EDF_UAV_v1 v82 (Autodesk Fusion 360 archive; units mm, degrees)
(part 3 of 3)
sketch "Sketch1" plane through (0, 0, 0) normal (0, 1, 0) x axis (1, 0, 0)
  line L1 (-11.4, 0) -> (-11.4, -16.82)
  line L2 (11.4, 0) -> (-11.4, 0)
  line L3 (11.4, -16.82) -> (11.4, 0)
  line L4 (16.2, -16.82) -> (11.4, -16.82)
  line L5 (16.2, -19.22) -> (16.2, -16.82)
  line L6 (11.4, -19.22) -> (16.2, -19.22)
  line L7 (11.4, -25.4) -> (11.4, -19.22)
  line L8 (-11.4, -25.4) -> (11.4, -25.4)
  line L9 (-11.4, -19.22) -> (-11.4, -25.4)
  line L10 (-16.2, -19.22) -> (-11.4, -19.22)
  line L11 (-16.2, -16.82) -> (-16.2, -19.22)
  line L12 (-16.2, -16.82) -> (-11.4, -16.82)
  line L13 (0, -22.5) -> (0, -1.75)
  point P1 (0, 0)
  point P3 (-11.4, 0)
  point P4 (11.4, 0)
  point P5 (11.4, -16.82)
  point P6 (16.2, -16.82)
  point P7 (16.2, -19.22)
  vertical L1
  perpendicular L1 L2
  perpendicular L2 L3
  perpendicular L3 L4
  perpendicular L4 L5
  perpendicular L5 L6
  perpendicular L6 L7
  perpendicular L7 L8
  perpendicular L8 L9
  perpendicular L9 L10
  perpendicular L10 L11
  perpendicular L11 L12
  equal L4 L12
  equal L2 L8
  collinear L1 L9
  equal L5 L11
  equal L1 L3
  coincident P1 L2
  symmetric L1 L3 L13
  dimension "d1" distance P3 P4 = 22.8
  dimension "d2" distance P4 P5 = 16.82
  dimension "d4" distance L5 L11 = 32.4
  dimension "d5" distance L2 L8 = 25.4
  dimension "d6" distance P6 P7 = 2.4
extrude "Extrude1" new body sketch "Sketch1" profile of L1 L2 L3 L4 L5 L6 L7 L8 L9 L10 L11 L12 distance 12
sketch "Sketch2" plane through (0, 0, 19.22) normal (0, 0, 1) x axis (-1, 0, 0)
  line L1 (11.4, -6) -> (11.4, 6)
  line L2 (16.2, -6) -> (11.4, -6)
  line L3 (16.2, 6) -> (16.2, -6)
  line L4 (11.4, 6) -> (16.2, 6)
  line L5 (0, -22.5) -> (0, -1.75)
  line L6 (-14.2, 0) -> (14.2, 0)
  line L7 (-22.5, 0) -> (-1.75, 0)
  circle C1 centre (14.2, 0) radius 1.25
  circle C2 centre (-14.2, 0) radius 1.25
  point P6 (14.2, 0)
  point P7 (-14.2, 0)
  point P10 (14.2, 0)
  point P11 (-14.2, 0)
  equal C1 C2
  symmetric P6 P7 L5
  coincident P6 P10
  coincident P7 P11
  collinear L6 L7
  dimension "d9" diameter C2 = 2.5
  dimension "d10" distance P6 P7 = 28.4
extrude "Extrude2" cut sketch "Sketch2" profile of C1 C2 L7 no distance stored
sketch "Sketch3" plane through (0, 0, 25.4) normal (0, 0, 1) x axis (-1, 0, 0)
  line L1 (-11.4, -6) -> (-11.4, 6)
  line L2 (11.4, -6) -> (-11.4, -6)
  line L3 (11.4, 6) -> (11.4, -6)
  line L4 (-11.4, 6) -> (11.4, 6)
  line L5 (0.4768, -1.75) -> (-0.6, -1.75)
  line L6 (0.4768, 1.75) -> (-0.6, 1.75)
  line L7 (-22.5, 0) -> (-1.75, 0)
  arc A1 centre (-0.6, 0) radius 1.75 clockwise from (-0.6, -1.75) to (-0.6, 1.75)
  arc A2 centre (5.4, 0) radius 5.225 clockwise from (0.4768, 1.75) to (0.4768, -1.75)
  point P7 (-0.6, 0)
  point P6 (5.4, 0)
  horizontal L5
  parallel L5 L6
  tangent L5 A1
  tangent L6 A1
  coincident P7 L7
  coincident P6 L7
  dimension "d14" diameter A2 = 10.45
  dimension "d15" distance L1 P6 = 16.8
  dimension "d21" diameter A1 = 3.5
  dimension "d22" distance P6 P7 = 6
extrude "Extrude4" cut sketch "Sketch3" profile of L1 L2 L3 L4 A2 against normal blind 0.5
sketch "Sketch5" plane through (0, 0, 25.4) normal (0, 0, 1) x axis (-1, 0, 0)
  line L1 (0.4768, -1.75) -> (-0.6, -1.75)
  line L2 (0.4768, 1.75) -> (-0.6, 1.75)
  circle C1 centre (5.4, 0) radius 4.5
  arc A1 centre (5.4, 0) radius 5.225 clockwise from (0.4768, 1.75) to (0.4768, -1.75)
  arc A2 centre (5.4, 0) radius 5.225 clockwise from (0.4768, 1.75) to (0.4768, -1.75)
  arc A3 centre (-0.6, 0) radius 1.75 clockwise from (-0.6, -1.75) to (-0.6, 1.75)
  concentric C1 A1
  dimension "d23" diameter C1 = 9
extrude "Extrude6" cut sketch "Sketch5" against normal blind 0.3
chamfer "Chamfer1" distance 0.5
chamfer "Chamfer2" distance 4 distance 1.5
sketch "Sketch6" plane through (0, 0, 25.4) normal (0, 0, 1) x axis (-1, 0, 0)
  circle C1 centre (5.4, 0) radius 4.5
  circle C2 centre (5.4, 0) radius 2.5
  concentric C1 C2
  dimension "d29" diameter C2 = 5
extrude "Extrude7" add sketch "Sketch6" profile of C2 along normal blind 2.8
chamfer "Chamfer3" distance 0.1
work_axis "WorkAxis1"
hole "Hole1" HoleDepth 3 HoleDiameter 1.271 TipAngle 118
sketch "Sketch1" plane through (0, 0, 28.2) normal (0, 0, 1) x axis (-1, 0, 0)
  circle C1 centre (5.4, 0) radius 2.5
  circle C2 centre (5.4, 0) radius 9.95
  circle C3 centre (5.4, 0) radius 3.5
  circle C4 centre (5.4, 0) radius 0.6355
  circle C5 centre (5.4, 0) radius 0.6355
  circle C6 centre (5.4, 0) radius 2.5
  concentric C1 C2
  concentric C1 C3
  concentric C1 C4
  equal C4 C5
  equal C1 C6
  concentric C3 C6
  dimension "d36" diameter C2 = 19.9
  dimension "d37" diameter C3 = 7
extrude "Extrude1" new body sketch "Sketch1" profile of C1 C3 against normal blind 2.4
extrude "Extrude2" add sketch "Sketch1" profile of C1 C2 C3 C4 C5 along normal blind 1.35
chamfer "Chamfer1" distance 1
sketch "Sketch2" plane through (0, 0, 29.55) normal (0, 0, 1) x axis (-1, 0, 0)
  line L1 (20.6977, 0) -> (5.4, 0)
  circle C1 centre (5.4, 0) radius 9.95
  circle C2 centre (5.4, 0) radius 1.6355
  circle C3 centre (5.4, 0) radius 4.5
  circle C4 centre (5.4, 0) radius 6.5
  circle C5 centre (5.4, 0) radius 8.5
  circle C6 centre (13.9, 0) radius 0.5
  circle C7 centre (11.9, 0) radius 0.5
  circle C8 centre (9.9, 0) radius 0.5
  point P4 (5.4, 0)
  point P6 (5.4, 0)
  point P8 (13.9, 0)
  point P9 (11.9, 0)
  point P10 (9.9, 0)
  concentric C1 C3
  concentric C3 C4
  concentric C3 C5
  coincident P4 P6
  horizontal L1
  coincident C5 P8
  coincident L1 P8
  coincident L1 P9
  coincident C4 P9
  coincident L1 P10
  coincident C3 P10
  equal C6 C7
  equal C6 C8
  dimension "d43" diameter C3 = 9
  dimension "d44" diameter C4 = 13
  dimension "d45" diameter C5 = 17
  dimension "d46" diameter C6 = 1
extrude "Extrude3" cut sketch "Sketch2" profile of C6 C7 C8 to an object
circular_pattern "C-Pattern1" TotalAngle 360
position "Position1"
joint "Assemble1" alignAngle 0 alignOffsetX 0 alignOffsetY 0 alignOffsetZ 0
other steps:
thread "Thread1"
create_component "CreateComponent1"
joint_origin "JointOrigin1"
joint_origin "JointOrigin1"

design "UAV_test_rig"
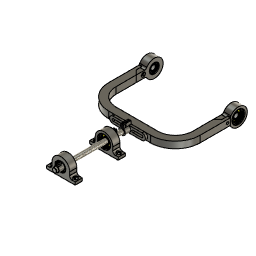
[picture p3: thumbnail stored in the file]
sketch "Sketch1" plane through (0, 0, 0) normal (0, 1, 0) x axis (1, 0, 0)
  line L1 (0, -39) -> (0, 16)
  line L2 (-16, -5) -> (-16, -16)
  line L3 (-26, -5) -> (-16, -5)
  line L4 (-26, 0) -> (-26, -5)
  line L5 (26, 0) -> (-26, 0)
  line L6 (26, -5) -> (26, 0)
  line L7 (16, -5) -> (26, -5)
  line L8 (16, -16) -> (16, -5)
  circle C1 centre (0, -16) radius 11.1
  arc A1 centre (0, -16) radius 16 clockwise from (16, -16) to (-16, -16)
  circle C2 centre (0, -16) radius 9
  point P1 (0, 0)
  point P2 (0, -16)
  point P8 (-26, -5)
  point P9 (-26, 0)
  vertical L1
  coincident P1 L1
  coincident P2 L1
  concentric C1 A1
  vertical L2
  perpendicular L2 L3
  perpendicular L3 L4
  perpendicular L1 L5
  perpendicular L3 L6
  perpendicular L1 L7
  tangent L2 A1
  tangent L8 A1
  vertical L8
  equal L3 L7
  equal L4 L6
  coincident P1 L5
  concentric C1 C2
  dimension "d1" diameter C1 = 22.2
  dimension "d2" distance P8 P9 = 5
  dimension "d3" distance L4 L6 = 52
  dimension "d4" distance P2 L5 = 16
  dimension "d10" diameter C2 = 18
  dimension "d68" diameter A1 = 32
extrude "Extrude1" new body sketch "Sketch1" profile of C1 A1 L2 L3 L4 L5 L6 L7 L8 along normal blind 13
fillet "Fillet1" radius 5
extrude "Extrude3" cut sketch "Sketch1" profile of C2 no distance stored
extrude "Extrude2" cut sketch "Sketch1" profile of C1 along normal blind 11
chamfer "Chamfer1" distance 1
chamfer "Chamfer2" distance 1 Rotate Angle 10
work_plane "WorkPlane2" AlongDistance 16
sketch "Sketch3" plane through (0, 0, 16) normal (0, 0, 1) x axis (1, 0, 0)
  line L1 (11.5, 3.9) -> (11.1, 3.9)
  line L2 (11.5, 2.8) -> (11.5, 3.9)
  line L3 (11.1, 2.8) -> (11.5, 2.8)
  line L4 (11.1, 3.9) -> (11.1, 2.8)
  line L5 (-11.1, 11) -> (11.1, 11)
  line L6 (11.1, -3.2011) -> (11.1, 11)
  line L7 (0, -3.5) -> (0, 0)
  line L8 (11.1, 2.4) -> (11.5, 2.8)
  line L9 (11.1, 2.8) -> (11.1, 2.4)
  point P6 (11.1, 11)
  point P8 (11.1, 11)
  point P1 (0, 0)
  point P10 (0, 0)
  point P12 (11.1, 2.4)
  point P3 (11.5, 3.9)
  point P4 (11.5, 2.8)
  horizontal L1
  vertical L2
  horizontal L3
  vertical L4
  coincident P6 P8
  perpendicular L5 L6
  collinear L4 L6
  coincident P1 P10
  vertical L7
  coincident L6 P12
  dimension "d17" distance L1 L5 = 7.1
  dimension "d18" = 23
  dimension "d19" distance P3 P4 = 1.1
  dimension "d20" angle L2 L8 = 45
revolve "Revolve1" sketch "Sketch3" AlongAngle 360
sketch "Sketch4" plane through (0, 0, 5) normal (0, 0, 1) x axis (-1, 0, 0)
  line L1 (21, 0) -> (26, 0)
  line L2 (26, -13) -> (21, -13)
  line L3 (26, 0) -> (26, -13)
  line L4 (23.75, -5.5) -> (23.75, -7.5)
  line L5 (19.25, -7.5) -> (19.25, -5.5)
  line L6 (21.5, -5.5) -> (21.5, -7.5)
  line L7 (20.5, -6.5) -> (22.5, -6.5)
  line L8 (21, -13) -> (21, 0)
  line L9 (25.5, -5.5) -> (25.5, -7.5)
  line L10 (17.5, -7.5) -> (17.5, -5.5)
  line L11 (21.5, -5.5) -> (21.5, -7.5)
  line L12 (-37.9338, -6.5) -> (-14.0662, -6.5)
  line L13 (-26, -13) -> (-26, 0)
  line L14 (-21, -8.75) -> (-22, -8.75)
  line L15 (-22, -4.25) -> (-21, -4.25)
  line L16 (-21, -6.5) -> (-22, -6.5)
  line L17 (-22, -2.5) -> (-21, -2.5)
  line L18 (-21, -10.5) -> (-22, -10.5)
  line L19 (-22, -6.5) -> (-21, -6.5)
  line L20 (-21.5, -1.6464) -> (-21.5, -11.3536)
  arc A1 centre (21.5, -5.5) radius 2.25 clockwise from (19.25, -5.5) to (23.75, -5.5)
  arc A2 centre (21.5, -7.5) radius 2.25 clockwise from (23.75, -7.5) to (19.25, -7.5)
  arc A3 centre (21.5, -5.5) radius 4 clockwise from (17.5, -5.5) to (25.5, -5.5)
  arc A4 centre (21.5, -7.5) radius 4 clockwise from (25.5, -7.5) to (17.5, -7.5)
  arc A5 centre (-21, -6.5) radius 2.25 clockwise from (-21, -4.25) to (-21, -8.75)
  arc A6 centre (-22, -6.5) radius 2.25 clockwise from (-22, -8.75) to (-22, -4.25)
  arc A7 centre (-22, -6.5) radius 4 clockwise from (-22, -10.5) to (-22, -2.5)
  arc A8 centre (-21, -6.5) radius 4 clockwise from (-21, -2.5) to (-21, -10.5)
  point P11 (21.5, -5.5)
  point P19 (21.5, -5.5)
  point P10 (21.5, -7.5)
  point P18 (21.5, -7.5)
  point P29 (-21, -6.5)
  point P28 (-22, -6.5)
  point P35 (-22, -6.5)
  point P34 (-21, -6.5)
  tangent L4 A1
  tangent A1 L5
  parallel L4 L5
  tangent L5 A2
  tangent L4 A2
  parallel L3 L6
  horizontal L7
  midpoint L6 L7
  symmetric L1 L2 L7
  tangent L9 A3
  tangent A3 L10
  parallel L9 L10
  tangent L10 A4
  tangent L9 A4
  coincident P11 P19
  perpendicular L7 L11
  coincident P10 P18
  horizontal L12
  midpoint L12 L13
  tangent L14 A5
  tangent A5 L15
  parallel L14 L15
  tangent L15 A6
  tangent L14 A6
  coincident L12 P29
  parallel L12 L16
  equal A2 A6
  tangent L17 A7
  tangent A7 L18
  parallel L17 L18
  tangent L18 A8
  tangent L17 A8
  coincident P28 P35
  parallel L16 L19
  coincident P29 P34
  equal A4 A7
  perpendicular L17 L20
  midpoint L19 L20
  dimension "d22" diameter A2 = 4.5
  dimension "d23" distance P10 P11 = 2
  dimension "d24" distance L3 L6 = 4.5
  dimension "d28" diameter A4 = 8
  dimension "d33" distance P28 P29 = 1
  dimension "d34" distance L13 L20 = 4.5
extrude "Extrude5" cut sketch "Sketch4" profile of L4 A1 L5 A2 L8 L14 A5 L15 A6 no distance stored
extrude "Extrude6" cut sketch "Sketch4" profile of L4 A1 L5 A2 L8 L9 A3 L10 A4 L14 A5 L15 A6 L17 A7 L18 A8 no distance stored
sketch "Sketch1" plane through (0, 3.9, 0) normal (0, -1, 0) x axis (1, 0, 0)
  line L1 (-5.9146, 1.7208) -> (0, 16)
  line L2 (5.4835, 2.7616) -> (0, 16)
  line L3 (0, 22.5) -> (0, 1.75)
  line L4 (0, 3.5) -> (0, 30)
  circle C1 centre (0, 16) radius 11.1
  circle C2 centre (0, 16) radius 11.5
  circle C3 centre (0, 16) radius 12.1
  circle C4 centre (-5.6108, 8.3339) radius 1
  arc A1 centre (-6.8161, 11.3521) radius 1 clockwise from (-6.4453, 10.4234) to (-7.6423, 10.7887)
  arc A2 centre (-5.6108, 8.3339) radius 2.25 clockwise from (-6.4453, 10.4234) to (-6.9397, 6.5182)
  arc A3 centre (0, 16) radius 9.25 clockwise from (-7.6423, 10.7887) to (0, 25.25)
  arc A4 centre (0, 16) radius 11.75 clockwise from (4.4965, 5.1444) to (-4.4965, 5.1444)
  arc A5 centre (0, 16) radius 11.75 clockwise from (-6.9397, 6.5182) to (0, 27.75)
  arc A6 centre (0, 16) radius 11.75 clockwise from (0, 27.75) to (6.9397, 6.5182)
  arc A7 centre (0, 16) radius 9.25 clockwise from (0, 25.25) to (7.6423, 10.7887)
  arc A8 centre (6.8161, 11.3521) radius 1 clockwise from (7.6423, 10.7887) to (6.4453, 10.4234)
  arc A9 centre (5.6108, 8.3339) radius 2.25 clockwise from (6.9397, 6.5182) to (6.4453, 10.4234)
  circle C5 centre (5.6108, 8.3339) radius 1
  point P4 (0, 16)
  point P5 (0, 16)
  point P3 (0, 16)
  point P7 (0, 16)
  point P18 (-4.4965, 5.1444)
  point P17 (0, 16)
  point P20 (0, 3.5)
  point P21 (4.4965, 5.1444)
  point P22 (0, 27.75)
  point P24 (0, 25.25)
  point P13 (-6.4453, 10.4234)
  point P32 (6.4453, 10.4234)
  point P14 (-7.6423, 10.7887)
  point P30 (7.6423, 10.7887)
  point P15 (-6.9397, 6.5182)
  point P27 (6.9397, 6.5182)
  point P26 (0, 27.75)
  point P29 (0, 25.25)
  concentric C3 A4
  coincident P4 P5
  coincident P3 P7
  tangent L1 A2
  concentric C4 A2
  tangent A2 A4
  coincident L1 P18
  tangent A1 A2
  tangent A1 A3
  coincident P5 P17
  coincident L3 P20
  parallel L3 L4
  coincident L2 P21
  coincident L4 P22
  concentric A4 A5
  coincident L4 P24
  tangent A2 A5
  symmetric C4 L4 C5
  symmetric P13 L4 P32
  symmetric P14 L4 P30
  symmetric A1 L4 A8
  symmetric P15 L4 P27
  symmetric A2 L4 A9
  symmetric A3 L4 A7
  symmetric L4 P22 P26
  symmetric L4 A5 A6
  symmetric L4 P24 P29
  dimension "d40" angle L1 L2 = 45
  dimension "d42" diameter C4 = 2
  dimension "d44" radius A1 = 1
  dimension "d45" diameter A2 = 4.5
  dimension "d47" diameter A5 = 23.5
  dimension "d48" distance A3 A5 = 2.5
extrude "Extrude1" new body sketch "Sketch1" profile of C1 C2 A5 A3 A2 C4 A1 A6 A7 A8 A9 C5 along normal blind 1
copy_paste "CopyPaste1"
base_feature "Base Feature1"
base_feature "Base Feature1"
base_feature "Base Feature1"
as_built_joint "As-built1"
ground "Ground1"
joint "Assemble2" alignAngle 90 alignOffsetX 0 alignOffsetY 0 alignOffsetZ 0
sketch "Sketch1" plane through (0, 0, 0) normal (0, 1, 0) x axis (1, 0, 0)
  circle C1 centre (0, 0) radius 4
  point P1 (0, 0)
  point P2 (0, 0)
  coincident P1 P2
  dimension "d59" diameter C1 = 8
extrude "Extrude1" new body sketch "Sketch1" along normal blind 150
chamfer "Chamfer1" distance 0.5 Rotate Angle 45
joint "Assemble1" alignAngle 90 alignOffsetX 0 alignOffsetY 0 alignOffsetZ 94
sketch "Sketch1" plane through (0, 0, 0) normal (0, 0, 1) x axis (1, 0, 0)
  line L1 (38, 0) -> (0, 0)
  line L2 (83, 100) -> (83, 45)
  line L3 (70, 100) -> (83, 100)
  line L4 (0, 93.0838) -> (0, 0)
  line L5 (38, 13) -> (0, 13)
  line L6 (70, 100) -> (70, 45)
  line L7 (-83, 100) -> (-83, 45)
  line L8 (-70, 100) -> (-83, 100)
  line L9 (-70, 100) -> (-70, 45)
  line L10 (-38, 13) -> (0, 13)
  line L11 (-38, 0) -> (0, 0)
  arc A1 centre (38, 45) radius 45 clockwise from (83, 45) to (38, 0)
  arc A2 centre (38, 45) radius 32 clockwise from (70, 45) to (38, 13)
  arc A3 centre (-38, 45) radius 32 clockwise from (-38, 13) to (-70, 45)
  arc A4 centre (-38, 45) radius 45 clockwise from (-38, 0) to (-83, 45)
  point P1 (0, 0)
  point P2 (0, 0)
  point P15 (0, 0)
  point P14 (0, 0)
  point P3 (38, 0)
  point P24 (-38, 0)
  point P4 (83, 45)
  point P13 (-83, 45)
  point P6 (83, 100)
  point P23 (-83, 100)
  point P7 (0, 13)
  point P17 (0, 13)
  point P8 (70, 45)
  point P22 (-70, 45)
  point P9 (70, 100)
  point P18 (-70, 100)
  point P10 (0, 93.0838)
  point P16 (0, 93.0838)
  point P11 (38, 13)
  point P19 (-38, 13)
  tangent L1 A1
  vertical L2
  perpendicular L1 L4
  vertical L4
  coincident P1 L4
  coincident P1 P2
  tangent A1 L2
  horizontal L3
  symmetric P1 L4 P15
  symmetric P2 L4 P14
  symmetric P3 L4 P24
  symmetric P4 L4 P13
  symmetric A1 L4 A4
  symmetric P6 L4 P23
  symmetric P7 L4 P17
  symmetric P8 L4 P22
  symmetric P9 L4 P18
  symmetric P10 L4 P16
  symmetric L4 P11 P19
  symmetric L4 A2 A3
  dimension "d69" = -13
  dimension "d70" = 140
  dimension "d71" distance P1 P6 = 100
  dimension "d72" radius A1 = 45
extrude "Extrude1" new body sketch "Sketch1" profile of L1 A1 L2 L5 L6 A2 L3 L7 A3 L8 L9 A4 L10 L11 distance 6
sketch "Sketch3" plane through (0, 0, 0) normal (0, -1, 0) x axis (1, 0, 0)
  line L1 (38, -6) -> (-38, -6)
  line L2 (38, 6) -> (38, -6)
  line L3 (-38, 6) -> (38, 6)
  line L4 (-38, -6) -> (-38, 6)
  circle C1 centre (0, 0) radius 6
  circle C2 centre (0, 0) radius 4.05
  point P1 (0, 0)
  point P3 (0, 0)
  coincident P1 P3
  dimension "d79" diameter C2 = 8.1
extrude "Extrude3" cut sketch "Sketch3" profile of C2 no distance stored
joint "Assemble2" alignAngle 0 alignOffsetX 0 alignOffsetY 0 alignOffsetZ 0
sketch "Sketch7" plane through (0, 0, 6) normal (0, 0, 1) x axis (-1, 0, 0)
  line L1 (-83, -100) -> (-83, -45)
  line L2 (-70, -100) -> (-83, -100)
  line L3 (-70, -45) -> (-70, -100)
  line L4 (38, -13) -> (-38, -13)
  line L5 (70, -100) -> (70, -45)
  line L6 (83, -100) -> (70, -100)
  line L7 (83, -45) -> (83, -100)
  line L8 (-38, 0) -> (38, 0)
  line L9 (-78, -100) -> (-70, -100)
  line L10 (-78, -90) -> (-78, -100)
  line L11 (-70, -100) -> (-70, -90)
  line L12 (-70, -82) -> (-78, -90)
  line L13 (-70, -90) -> (-70, -82)
  line L14 (-62.5, -90) -> (-78, -90)
  arc A1 centre (-38, -45) radius 45 clockwise from (-83, -45) to (-38, 0)
  arc A2 centre (-38, -45) radius 32 clockwise from (-70, -45) to (-38, -13)
  arc A3 centre (38, -45) radius 32 clockwise from (38, -13) to (70, -45)
  arc A4 centre (38, -45) radius 45 clockwise from (38, 0) to (83, -45)
  point P17 (-70, -100)
  point P21 (-70, -82)
  point P18 (-78, -100)
  horizontal L9
  vertical L10
  vertical L11
  coincident L2 P17
  collinear L3 L11
  coincident L3 P21
  perpendicular L10 L14
  dimension "d105" distance P17 P18 = 8
  dimension "d111" angle L12 L14 = 45
  dimension "d118" distance L9 P21 = 18
extrude "Extrude8" cut sketch "Sketch7" profile of L2 L9 L10 L11 to an object
sketch "Sketch9" plane through (83, 0, 0) normal (1, 0, 0) x axis (0, 1, 0)
  line L1 (100, 6) -> (100, -6)
  line L2 (45, 6) -> (100, 6)
  line L3 (45, -6) -> (45, 6)
  line L4 (100, -6) -> (45, -6)
  line L5 (91.3635, 0) -> (105, 0)
  circle C1 centre (95, 0) radius 2.25
  point P8 (95, 0)
  perpendicular L1 L5
  coincident L5 P8
  symmetric L2 L4 L5
  dimension "d129" diameter C1 = 4.5
  dimension "d130" distance L1 P8 = 5
extrude "Extrude9" cut sketch "Sketch9" profile of C1 to an object
sketch "Sketch1" plane through (0, 0, 0) normal (0, 1, 0) x axis (1, 0, 0)
  line L1 (0, -39) -> (0, 16)
  line L2 (-6, 32.8324) -> (-6, 14.8324)
  line L3 (6, 32.8324) -> (-6, 32.8324)
  line L4 (6, 14.8324) -> (6, 32.8324)
  line L5 (22.5, 0) -> (1.75, 0)
  line L6 (0, -22.5) -> (0, -1.75)
  circle C1 centre (0, 0) radius 11.1
  arc A1 centre (0, 0) radius 16 clockwise from (6, 14.8324) to (-6, 14.8324)
  circle C2 centre (0, 0) radius 9
  point P2 (0, 0)
  point P5 (0, 0)
  point P6 (0, 0)
  point P9 (-6, 32.8324)
  point P10 (6, 32.8324)
  point P7 (6, 14.8324)
  vertical L1
  coincident P2 L1
  concentric C1 A1
  concentric C1 C2
  vertical L2
  horizontal L3
  vertical L4
  symmetric L1 L2 L4
  coincident P5 L5
  coincident P6 L6
  dimension "d1_1" diameter C1 = 22.2
  dimension "d10_1" diameter C2 = 18
  dimension "d68_1" diameter A1 = 32
  dimension "d116" distance P9 P10 = 12
  dimension "d117" distance P7 P10 = 18
extrude "Extrude1" new body sketch "Sketch1" profile of C1 A1 along normal blind 13 named "d6_1"
extrude "Extrude3" cut sketch "Sketch1" profile of C2 no distance stored
extrude "Extrude2" cut sketch "Sketch1" profile of C1 along normal blind 11 named "d8_1"
chamfer "Chamfer1" distance 1 named "d35_1"
chamfer "Chamfer2" distance 1 named "d36_1" Rotate Angle 10 named "d37_1"
sketch "Sketch3" plane through (0, 0, 0) normal (0, 0, 1) x axis (1, 0, 0)
  line L1 (11.5, 3.9) -> (11.1, 3.9)
  line L2 (11.5, 2.8) -> (11.5, 3.9)
  line L3 (11.1, 2.8) -> (11.5, 2.8)
  line L4 (11.1, 3.9) -> (11.1, 2.8)
  line L5 (-11.1, 11) -> (11.1, 11)
  line L6 (11.1, -3.2011) -> (11.1, 11)
  line L7 (0, -3.5) -> (0, 0)
  line L8 (11.1, 2.4) -> (11.5, 2.8)
  line L9 (11.1, 2.8) -> (11.1, 2.4)
  point P6 (11.1, 11)
  point P8 (11.1, 11)
  point P1 (0, 0)
  point P10 (0, 0)
  point P12 (11.1, 2.4)
  point P3 (11.5, 3.9)
  point P4 (11.5, 2.8)
  horizontal L1
  vertical L2
  horizontal L3
  vertical L4
  coincident P6 P8
  perpendicular L5 L6
  collinear L4 L6
  coincident P1 P10
  vertical L7
  coincident L6 P12
  dimension "d17_1" distance L1 L5 = 7.1
  dimension "d18_1" = 23
  dimension "d19_1" distance P3 P4 = 1.1
  dimension "d20_1" angle L2 L8 = 45
revolve "Revolve1" sketch "Sketch3" AlongAngle 360 named "d21_1"
sketch "Sketch1" plane through (0, 3.9, 0) normal (0, -1, 0) x axis (1, 0, 0)
  line L1 (-0.2227, -0.5376) -> (0, 0)
  line L2 (-0.153, 0.3693) -> (0, 0)
  line L3 (0, 22.5) -> (0, 1.75)
  line L4 (0, 3.5) -> (0, 30)
  circle C1 centre (0, 0) radius 12.1
  circle C2 centre (-5.6108, -7.6661) radius 1
  arc A1 centre (-6.8161, -4.6479) radius 1 clockwise from (-6.4453, -5.5766) to (-7.6423, -5.2113)
  arc A2 centre (-5.6108, -7.6661) radius 2.25 clockwise from (-6.4453, -5.5766) to (-6.9397, -9.4818)
  arc A3 centre (0, 0) radius 9.25 clockwise from (-7.6423, -5.2113) to (0, 9.25)
  arc A4 centre (0, 0) radius 11.75 clockwise from (-4.4965, 10.8556) to (-4.4965, -10.8556)
  arc A5 centre (0, 0) radius 11.75 clockwise from (-6.9397, -9.4818) to (0, 11.75)
  arc A6 centre (0, 0) radius 11.75 clockwise from (0, 11.75) to (6.9397, -9.4818)
  arc A7 centre (0, 0) radius 9.25 clockwise from (0, 9.25) to (7.6423, -5.2113)
  arc A8 centre (6.8161, -4.6479) radius 1 clockwise from (7.6423, -5.2113) to (6.4453, -5.5766)
  arc A9 centre (5.6108, -7.6661) radius 2.25 clockwise from (6.9397, -9.4818) to (6.4453, -5.5766)
  circle C3 centre (5.6108, -7.6661) radius 1
  circle C4 centre (0, 0) radius 11.5
  circle C5 centre (0, 0) radius 11.1
  point P3 (0, 0)
  point P4 (0, 0)
  point P2 (0, 0)
  point P6 (0, 0)
  point P17 (-4.4965, -10.8556)
  point P16 (0, 0)
  point P19 (0, 3.5)
  point P20 (-4.4965, 10.8556)
  point P21 (0, 11.75)
  point P23 (0, 9.25)
  point P12 (-6.4453, -5.5766)
  point P31 (6.4453, -5.5766)
  point P13 (-7.6423, -5.2113)
  point P29 (7.6423, -5.2113)
  point P14 (-6.9397, -9.4818)
  point P26 (6.9397, -9.4818)
  point P25 (0, 11.75)
  point P28 (0, 9.25)
  concentric C1 A4
  coincident P3 P4
  coincident P2 P6
  tangent L1 A2
  concentric C2 A2
  tangent A2 A4
  coincident L1 P17
  tangent A1 A2
  tangent A1 A3
  coincident P4 P16
  coincident L3 P19
  parallel L3 L4
  coincident L2 P20
  coincident L4 P21
  concentric A4 A5
  coincident L4 P23
  tangent A2 A5
  symmetric C2 L4 C3
  symmetric P12 L4 P31
  symmetric P13 L4 P29
  symmetric A1 L4 A8
  symmetric P14 L4 P26
  symmetric A2 L4 A9
  symmetric A3 L4 A7
  symmetric L4 P21 P25
  symmetric L4 A5 A6
  symmetric L4 P23 P28
  dimension "d40_1" angle L1 L2 = 45
  dimension "d42_1" diameter C2 = 2
  dimension "d44_1" radius A1 = 1
  dimension "d45_1" diameter A2 = 4.5
  dimension "d47_1" diameter A5 = 23.5
  dimension "d48_1" distance A3 A5 = 2.5
extrude "Extrude1" new body sketch "Sketch1" profile of C5 A5 A3 A2 C2 A1 A6 A7 A8 A9 C3 along normal blind 1 named "d49_1"
base_feature "Base Feature1"
base_feature "Base Feature1"
base_feature "Base Feature1"
as_built_joint "As-built1"
joint "Assemble2" alignAngle 90 named "d55_1" alignOffsetX 0 named "d56_1" alignOffsetY 0 named "d57_1" alignOffsetZ 0 named "d58_1"
as_built_joint "As-built1"
sketch "Sketch5" plane through (6, 0, 0) normal (1, 0, 0) x axis (0, 1, 0)
  line L1 (0, -32.8324) -> (0, -14.8324)
  line L2 (13, -32.8324) -> (0, -32.8324)
  line L3 (13, -14.8324) -> (13, -32.8324)
  line L4 (0, -14.8324) -> (13, -14.8324)
  line L5 (5, -14.8324) -> (0, -14.8324)
  line L6 (5, -24.8324) -> (5, -14.8324)
  line L7 (13, -32.8324) -> (5, -24.8324)
  point P2 (0, -14.8324)
  point P6 (0, -14.8324)
  point P4 (13, -32.8324)
  point P10 (13, -32.8324)
  point P7 (5, -14.8324)
  point P8 (5, -14.8324)
  point P5 (13, -14.8324)
  coincident P2 P6
  perpendicular L3 L5
  perpendicular L4 L6
  coincident P4 P10
  coincident P7 P8
  dimension "d120" angle L6 L7 = 45
  dimension "d138" distance P5 L6 = 8
extrude "Extrude7" cut sketch "Sketch5" profile of L1 L2 L4 L5 L6 L7 to an object
fillet "Fillet2" radius 5
joint "Assemble3" alignAngle 270 alignOffsetX 0 alignOffsetY 0 alignOffsetZ 0
sketch "Sketch6" plane through (0, 5, 0) normal (0, -1, 0) x axis (1, 0, 0)
  line L1 (-6, -24.8324) -> (-6, -17.8885)
  line L2 (6, -24.8324) -> (-6, -24.8324)
  line L3 (6, -17.8885) -> (6, -24.8324)
  line L4 (-7.0427, -14.8324) -> (7.0427, -14.8324)
  line L5 (0, -26.6742) -> (0, -19.8324)
  arc A1 centre (11, -17.8885) radius 5 clockwise from (6, -17.8885) to (7.0427, -14.8324)
  arc A2 centre (-11, -17.8885) radius 5 clockwise from (-7.0427, -14.8324) to (-6, -17.8885)
  circle C1 centre (0, -19.8324) radius 2.25
  point P10 (0, -19.8324)
  point P11 (0, -19.8324)
  coincident P10 P11
  vertical L5
  dimension "d131" diameter C1 = 4.5
  dimension "d132" distance L4 P10 = 5
extrude "Extrude8" cut sketch "Sketch6" profile of C1 along a picked direction to an object
sketch "Sketch7" plane through (0, 13, 0) normal (0, 1, 0) x axis (-1, 0, 0)
  line L1 (-6, -32.8324) -> (-6, -17.8885)
  line L2 (6, -32.8324) -> (-6, -32.8324)
  line L3 (6, -17.8885) -> (6, -32.8324)
  line L4 (0, -15.7332) -> (3.55, -17.7828)
  line L5 (-3.55, -17.7828) -> (0, -15.7332)
  line L6 (-3.55, -21.882) -> (-3.55, -17.7828)
  line L7 (0, -23.9316) -> (-3.55, -21.882)
  line L8 (3.55, -21.882) -> (0, -23.9316)
  line L9 (3.55, -17.7828) -> (3.55, -21.882)
  circle C1 centre (0, -19.8324) radius 2.25
  circle C2 centre (0, 0) radius 9
  arc A1 centre (0, 0) radius 16 clockwise from (-8.381, -13.6294) to (8.381, -13.6294)
  arc A2 centre (-11, -17.8885) radius 5 clockwise from (-8.381, -13.6294) to (-6, -17.8885)
  arc A3 centre (11, -17.8885) radius 5 clockwise from (6, -17.8885) to (8.381, -13.6294)
  point P2 (0, -19.8324)
  point P18 (0, -19.8324)
  coincident P2 P18
  vertical L9
  dimension "d139" distance L6 L9 = 7.1
extrude "Extrude9" cut sketch "Sketch7" profile of C1 L4 L5 L6 L7 L8 L9 along a picked direction blind -3.3
mirror "Mirror1" mirrorStitchTolerance 0.1
copy_paste "CopyPaste3"
joint "Assemble4" alignAngle -90 alignOffsetX 0 alignOffsetY 0 alignOffsetZ 0
sketch "Sketch8" plane through (0, 9.7, 0) normal (0, 1, 0) x axis (-1, 0, 0)
  line L1 (3.55, -17.7828) -> (3.55, -21.882)
  line L2 (0, -15.7332) -> (3.55, -17.7828)
  line L3 (-3.55, -17.7828) -> (0, -15.7332)
  line L4 (-3.55, -21.882) -> (-3.55, -17.7828)
  line L5 (0, -23.9316) -> (-3.55, -21.882)
  line L6 (3.55, -21.882) -> (0, -23.9316)
  circle C1 centre (0, -19.8324) radius 2.25
extrude "Extrude10" add sketch "Sketch8" along a picked direction blind -0.2
sketch "Sketch1" plane through (0, -90.2, 0) normal (0, -1, 0) x axis (1, 0, 0)
  circle C1 centre (0, 16) radius 3.5
  circle C2 centre (0, 16) radius 4.1
  circle C3 centre (0, 16) radius 5.1
  concentric C1 C2
  concentric C2 C3
  dimension "d148" diameter C2 = 8.2
  dimension "d149" distance C2 C3 = 1
extrude "Extrude1" new body sketch "Sketch1" profile of C2 C3 against normal blind 10
sketch "Sketch2" plane through (0, -90.2, 16) normal (0, -1, 0) x axis (1, 0, 0)
  line L1 (-2.5, 10.4452) -> (-2.5, 4.4452)
  line L2 (2.5, 10.4452) -> (-2.5, 10.4452)
  line L3 (2.5, 4.4452) -> (2.5, 10.4452)
  line L4 (0, 9.1) -> (0, 0)
  circle C1 centre (0, 0) radius 5.1
  circle C2 centre (0, 0) radius 4.1
  circle C3 centre (0, 0) radius 5.1
  point P2 (-2.5, 4.4452)
  point P5 (2.5, 4.4452)
  point P6 (0, 0)
  point P7 (0, 0)
  point P3 (-2.5, 10.4452)
  point P4 (2.5, 10.4452)
  vertical L1
  perpendicular L1 L2
  perpendicular L2 L3
  coincident P2 C1
  coincident P5 C1
  coincident P6 P7
  perpendicular L2 L4
  dimension "d152" distance P3 P4 = 5
  dimension "d153" distance P2 P3 = 6
extrude "Extrude3" add sketch "Sketch2" profile of L1 L2 L3 C1 C3 against normal blind 6
sketch "Sketch3" plane through (0, -90.2, 0) normal (0, -1, 0) x axis (1, 0, 0)
  line L1 (2.5, 26.4452) -> (2.5, 20.4452)
  line L2 (-2.5, 26.4452) -> (2.5, 26.4452)
  line L3 (-2.5, 20.4452) -> (-2.5, 26.4452)
  line L4 (0.5, 26.4452) -> (-0.5, 26.4452)
  line L5 (0.5, 20.0694) -> (0.5, 26.4452)
  line L6 (-0.5, 20.0694) -> (0.5, 20.0694)
  line L7 (-0.5, 26.4452) -> (-0.5, 20.0694)
  circle C1 centre (0, 16) radius 4.1
  arc A1 centre (0, 16) radius 5.1 clockwise from (2.5, 20.4452) to (-2.5, 20.4452)
  point P9 (0.5, 20.0694)
  point P7 (-0.5, 26.4452)
  point P10 (-0.5, 20.0694)
  point P8 (0.5, 26.4452)
  horizontal L4
  vertical L5
  horizontal L6
  vertical L7
  coincident C1 P9
  coincident L2 P7
  coincident C1 P10
  dimension "d158" distance P7 P8 = 1
extrude "Extrude4" cut sketch "Sketch3" profile of C1 L2 L4 L5 L7 to an object
sketch "Sketch4" plane through (-2.5, 0, 0) normal (-1, 0, 0) x axis (0, -1, 0)
  line L1 (90.2, 26.4452) -> (90.2, 20.4452)
  line L2 (84.2, 26.4452) -> (90.2, 26.4452)
  line L3 (84.2, 20.4452) -> (84.2, 26.4452)
  line L4 (90.2, 20.4452) -> (84.2, 20.4452)
  line L5 (88.3836, 25.4952) -> (89.5671, 23.4452)
  line L6 (86.0164, 25.4952) -> (88.3836, 25.4952)
  line L7 (84.8329, 23.4452) -> (86.0164, 25.4952)
  line L8 (86.0164, 21.3952) -> (84.8329, 23.4452)
  line L9 (88.3836, 21.3952) -> (86.0164, 21.3952)
  line L10 (89.5671, 23.4452) -> (88.3836, 21.3952)
  line L11 (87.2, 27.9452) -> (87.2, 23.4452)
  circle C1 centre (87.2, 23.4452) radius 1.2
  point P6 (87.2, 23.4452)
  point P13 (87.2, 23.4452)
  point P14 (87.2, 23.4452)
  coincident P6 P13
  horizontal L6
  coincident P6 P14
  vertical L11
  symmetric L1 L3 L11
  dimension "d161" diameter C1 = 2.4
  dimension "d163" distance L6 L9 = 4.1
  dimension "d164" distance L2 P6 = 3
extrude "Extrude5" cut sketch "Sketch4" profile of C1 to an object
extrude "Extrude6" cut sketch "Sketch4" profile of C1 L5 L6 L7 L8 L9 L10 against normal blind 0.5
sketch "Sketch1" plane through (0, 46.8, 0) normal (0, -1, 0) x axis (1, 0, 0)
  line L1 (26.5, 22) -> (-26.5, 22)
  line L2 (-26.5, 10) -> (26.5, 10)
  line L3 (38, 22) -> (-38, 22)
  line L4 (-38, 10) -> (38, 10)
  line L5 (0, 22.5) -> (0, 1.75)
  line L6 (-32.5, 28) -> (-32.5, 16)
  line L7 (32.5, 29) -> (32.5, 16)
  arc A1 centre (-26.5, 16) radius 6 clockwise from (-26.5, 10) to (-26.5, 22)
  arc A2 centre (26.5, 16) radius 6 clockwise from (26.5, 22) to (26.5, 10)
  point P14 (-32.5, 16)
  point P16 (32.5, 16)
  horizontal L1
  horizontal L2
  collinear L1 L3
  collinear L2 L4
  tangent L1 A1
  tangent L2 A1
  tangent L1 A2
  tangent L2 A2
  midpoint A1 P14
  tangent A1 L6
  perpendicular L3 L6
  midpoint A2 P16
  tangent A2 L7
  perpendicular L3 L7
  symmetric L5 A1 A2
  dimension "d206" distance L6 L7 = 65
extrude "Extrude1" new body sketch "Sketch1" profile of L1 L2 L3 L4 L5 A1 A2 along normal blind 4
sketch "Sketch2" plane through (0, 42.8, 0) normal (0, -1, 0) x axis (1, 0, 0)
  line L1 (-26.5, 22) -> (26.5, 22)
  line L2 (26.5, 10) -> (-26.5, 10)
  circle C1 centre (0, 16) radius 6
  arc A1 centre (-26.5, 16) radius 6 clockwise from (-26.5, 10) to (-26.5, 22)
  arc A2 centre (26.5, 16) radius 6 clockwise from (26.5, 22) to (26.5, 10)
  dimension "d173" diameter C1 = 12
extrude "Extrude2" add sketch "Sketch2" profile of C1 along normal blind 10
sketch "Sketch3" plane through (0, 32.8, 0) normal (0, -1, 0) x axis (1, 0, 0)
  line L1 (2.5, 21.4544) -> (-2.5, 21.4544)
  line L2 (2.5, 27.4544) -> (2.5, 21.4544)
  line L3 (-2.5, 27.4544) -> (2.5, 27.4544)
  line L4 (-2.5, 21.4544) -> (-2.5, 27.4544)
  circle C1 centre (0, 16) radius 6
  point P3 (-2.5, 21.4544)
  point P4 (2.5, 21.4544)
  point P5 (2.5, 27.4544)
  point P6 (-2.5, 27.4544)
  horizontal L1
  vertical L2
  horizontal L3
  vertical L4
  coincident C1 P3
  coincident C1 P4
  dimension "d177" distance P5 P6 = 5
  dimension "d178" distance P3 P6 = 6
extrude "Extrude3" add sketch "Sketch3" profile of C1 L2 L3 L4 to an object
sketch "Sketch4" plane through (-2.5, 0, 0) normal (-1, 0, 0) x axis (0, -1, 0)
  line L1 (-32.8, 27.4544) -> (-32.8, 21.4544)
  line L2 (-46.8, 27.4544) -> (-32.8, 27.4544)
  line L3 (-46.8, 22) -> (-46.8, 27.4544)
  line L4 (-32.8, 21.4544) -> (-42.8, 21.4544)
  line L5 (-39.1671, 24.4544) -> (-37.9836, 26.5044)
  line L6 (-37.9836, 22.4044) -> (-39.1671, 24.4544)
  line L7 (-35.6164, 22.4044) -> (-37.9836, 22.4044)
  line L8 (-34.4329, 24.4544) -> (-35.6164, 22.4044)
  line L9 (-35.6164, 26.5044) -> (-34.4329, 24.4544)
  line L10 (-37.9836, 26.5044) -> (-35.6164, 26.5044)
  line L11 (-36.8, 28.0631) -> (-36.8, 24.4544)
  line L12 (-42.8, 21.4544) -> (-42.8, 22)
  line L13 (-42.8, 22) -> (-46.8, 22)
  circle C1 centre (-36.8, 24.4544) radius 1.2
  point P6 (-36.8, 24.4544)
  point P13 (-36.8, 24.4544)
  point P14 (-36.8, 24.4544)
  coincident P6 P13
  coincident P6 P14
  perpendicular L2 L11
  horizontal L10
  dimension "d182" distance L7 L10 = 4.1
  dimension "d183" distance L2 P13 = 3
  dimension "d184" diameter C1 = 2.4
  dimension "d196" distance L1 L11 = 4
extrude "Extrude4" cut sketch "Sketch4" profile of C1 to an object
extrude "Extrude5" cut sketch "Sketch4" profile of C1 L5 L6 L7 L8 L9 L10 against normal blind 0.5
sketch "Sketch6" plane through (0, 32.8, 0) normal (0, -1, 0) x axis (1, 0, 0)
  line L1 (-2.5, 21.4544) -> (-2.5, 27.4544)
  line L2 (2.5, 27.4544) -> (2.5, 21.4544)
  line L3 (-2.5, 27.4544) -> (2.5, 27.4544)
  arc A1 centre (0, 16) radius 6 clockwise from (2.5, 21.4544) to (-2.5, 21.4544)
  circle C1 centre (0, 16) radius 4.05
  concentric A1 C1
  dimension "d192" diameter C1 = 8.1
extrude "Extrude7" cut sketch "Sketch6" profile of C1 to an object
sketch "Sketch5" plane through (0, 32.8, 0) normal (0, -1, 0) x axis (1, 0, 0)
  line L1 (2.5, 27.4544) -> (2.5, 21.4544)
  line L2 (-2.5, 27.4544) -> (2.5, 27.4544)
  line L3 (-2.5, 21.4544) -> (-2.5, 27.4544)
  line L4 (0.5, 27.4544) -> (-0.5, 27.4544)
  line L5 (0.5, 20.019) -> (0.5, 27.4544)
  line L6 (-0.5, 20.019) -> (0.5, 20.019)
  line L7 (-0.5, 27.4544) -> (-0.5, 20.019)
  arc A1 centre (0, 16) radius 6 clockwise from (2.5, 21.4544) to (-2.5, 21.4544)
  circle C1 centre (0, 16) radius 4.05
  point P7 (-0.5, 27.4544)
  point P10 (-0.5, 20.019)
  point P9 (0.5, 20.019)
  point P8 (0.5, 27.4544)
  horizontal L4
  vertical L5
  horizontal L6
  vertical L7
  coincident L2 P7
  coincident P10 C1
  coincident P9 C1
  dimension "d189" distance P7 P8 = 1
extrude "Extrude6" cut sketch "Sketch5" profile of L2 L4 L5 L7 to an object
sketch "Sketch7" plane through (0, 42.8, 0) normal (0, -1, 0) x axis (1, 0, 0)
  line L1 (-2.5, 22) -> (-2.5, 21.4544)
  line L2 (-10, 13.95) -> (-26, 13.95)
  line L3 (-26, 18.05) -> (-10, 18.05)
  line L4 (-10, 16) -> (-26, 16)
  line L5 (0, 22.5) -> (0, 1.75)
  line L6 (-26.5, 22) -> (-2.5, 22)
  line L7 (0, 10) -> (-26.5, 10)
  arc A1 centre (0, 16) radius 6 clockwise from (0, 10) to (-2.5, 21.4544)
  arc A2 centre (-10, 16) radius 2.05 clockwise from (-10, 18.05) to (-10, 13.95)
  arc A3 centre (-26, 16) radius 2.05 clockwise from (-26, 13.95) to (-26, 18.05)
  arc A4 centre (-26.5, 16) radius 6 clockwise from (-26.5, 10) to (-26.5, 22)
  point P10 (-26, 16)
  point P11 (-10, 16)
  tangent L2 A2
  tangent A2 L3
  parallel L2 L3
  tangent L3 A3
  tangent L2 A3
  horizontal L4
  dimension "d197" distance L2 L3 = 4.1
  dimension "d198" distance P10 P11 = 16
  dimension "d199" distance P11 L5 = 10
extrude "Extrude8" cut sketch "Sketch7" profile of L2 A2 L3 A3 to an object
mirror "Mirror1" mirrorStitchTolerance 0.1
joint "Assemble5" alignAngle 0 alignOffsetX 0 alignOffsetY 0 alignOffsetZ 0
sketch "Sketch10" plane through (0, 13, 0) normal (0, 1, 0) x axis (-1, 0, 0)
  line L1 (38, 6) -> (38, -6)
  line L2 (-38, 6) -> (38, 6)
  line L3 (-38, -6) -> (-38, 6)
  line L4 (38, -6) -> (-38, -6)
  line L5 (-20.0496, 3.55) -> (-15.9504, 3.55)
  line L6 (-22.0992, 0) -> (-20.0496, 3.55)
  line L7 (-20.0496, -3.55) -> (-22.0992, 0)
  line L8 (-15.9504, -3.55) -> (-20.0496, -3.55)
  line L9 (-13.9008, 0) -> (-15.9504, -3.55)
  line L10 (-15.9504, 3.55) -> (-13.9008, 0)
  line L11 (-9, 0) -> (-25.659, 0)
  line L12 (0, 6.5) -> (0, -14.25)
  circle C1 centre (0, 0) radius 4.05
  circle C2 centre (-18, 0) radius 2.05
  point P7 (-18, 0)
  point P14 (-18, 0)
  coincident P7 P14
  horizontal L5
  horizontal L11
  coincident P14 L11
  symmetric L2 L4 L11
  dimension "d211" diameter C2 = 4.1
  dimension "d212" distance P7 L12 = 18
  dimension "d213" distance L5 L8 = 7.1
extrude "Extrude11" cut sketch "Sketch10" profile of C2 to an object
extrude "Extrude12" cut sketch "Sketch10" profile of C2 L5 L6 L7 L8 L9 L10 against normal blind 3.3
mirror "Mirror2" mirrorStitchTolerance 0.1
sketch "Sketch11" plane through (0, 13, 0) normal (0, 1, 0) x axis (-1, 0, 0)
  line L1 (20.0496, 3.55) -> (15.9504, 3.55)
  line L2 (22.0992, 0) -> (20.0496, 3.55)
  line L3 (20.0496, -3.55) -> (22.0992, 0)
  line L4 (15.9504, -3.55) -> (20.0496, -3.55)
  line L5 (13.9008, 0) -> (15.9504, -3.55)
  line L6 (15.9504, 3.55) -> (13.9008, 0)
  line L7 (-15.9504, 3.55) -> (-20.0496, 3.55)
  line L8 (-13.9008, 0) -> (-15.9504, 3.55)
  line L9 (-15.9504, -3.55) -> (-13.9008, 0)
  line L10 (-20.0496, -3.55) -> (-15.9504, -3.55)
  line L11 (-22.0992, 0) -> (-20.0496, -3.55)
  line L12 (-20.0496, 3.55) -> (-22.0992, 0)
  line L13 (38, 6) -> (38, -6)
  line L14 (-38, 6) -> (38, 6)
  line L15 (-38, -6) -> (-38, 6)
  line L16 (38, -6) -> (-38, -6)
  line L17 (8, -4.05) -> (-8, -4.05)
  line L18 (-8, 4.05) -> (8, 4.05)
  line L19 (8, 0) -> (-8, 0)
  line L20 (0, 6.5) -> (0, -14.25)
  circle C1 centre (0, 0) radius 4.05
  arc A1 centre (8, 0) radius 4.05 clockwise from (8, 4.05) to (8, -4.05)
  arc A2 centre (-8, 0) radius 4.05 clockwise from (-8, -4.05) to (-8, 4.05)
  point P23 (-8, 0)
  point P24 (8, 0)
  tangent L17 A1
  tangent A1 L18
  parallel L17 L18
  tangent L18 A2
  tangent L17 A2
  horizontal L19
  symmetric A1 A2 L20
  symmetric L14 L16 L19
  dimension "d220" distance L17 L18 = 8.1
  dimension "d221" distance P23 P24 = 16
extrude "Extrude13" cut sketch "Sketch11" profile of C1 L17 A1 L18 A2 to an object
joint "Assemble6" alignAngle -90 alignOffsetX 0 alignOffsetY 0 alignOffsetZ 0
copy_paste "CopyPaste4"
as_built_joint "As-built1"
joint "Assemble8" alignAngle 90 alignOffsetX 0 alignOffsetY 0 alignOffsetZ 20
joint "Assemble9" alignAngle -90 alignOffsetX 0 alignOffsetY 0 alignOffsetZ 0
joint_origin "JointOrigin1"
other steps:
create_component "CreateComponent1"
create_component "CreateComponent1"
create_component "CreateComponent2"
create_component "CreateComponent1"
create_component "CreateComponent1"
create_component "CreateComponent2"
create_component "CreateComponent3"
joint_origin "JointOrigin2"
joint_origin "JointOrigin2"
create_component "CreateComponent2"
joint_origin "JointOrigin1"
joint_origin "JointOrigin1"
create_component "CreateComponent3"
joint_origin "JointOrigin1"
joint_origin "JointOrigin2"
create_component "CreateComponent1"
create_component "CreateComponent2"
create_component "CreateComponent1"
create_component "CreateComponent1"
create_component "CreateComponent2"
create_component "CreateComponent3"
joint_origin "JointOrigin2"
joint_origin "JointOrigin2"
create_component "CreateComponent4"
joint_origin "JointOrigin3"
joint_origin "JointOrigin2"
joint_origin "JointOrigin4"
joint_origin "JointOrigin3"
create_component "CreateComponent5"
create_component "CreateComponent6"
joint_origin "JointOrigin1"
joint_origin "JointOrigin4"
joint_origin "JointOrigin1"
joint_origin "JointOrigin2"
joint_origin "JointOrigin5"
joint_origin "JointOrigin4"
joint_origin "JointOrigin3"
joint_origin "JointOrigin6"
